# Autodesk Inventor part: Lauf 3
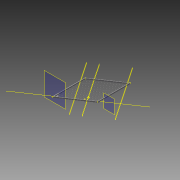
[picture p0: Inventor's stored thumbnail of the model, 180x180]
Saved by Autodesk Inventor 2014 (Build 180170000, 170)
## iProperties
Created: 2013-09
Part Number: Lauf 3
Material: Edelstahl
Document SubType Name: Modeling
Designer: Stefan Tammegger
Mass: 17798.4 g
Surface Area: 20213.9 cm^2
Volume: 2202.78 cm^3
Density: 8.08 g/cm^3
Appearance: Halbpoliert
Author: Stefan Tammegger
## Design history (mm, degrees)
node "Blöcke"
  sketch "FR 50 30 2"
    geometry: L1 (-39.377, 51.937)-(-65.377, 51.937); L2 (-67.377, 53.937)-(-67.377, 99.937); L3 (-65.377, 101.937)-(-39.377, 101.937); L4 (-37.377, 99.937)-(-37.377, 53.937); L5 (-39.377, 53.937)-(-65.377, 53.937); L6 (-65.377, 53.937)-(-65.377, 99.937); L7 (-65.377, 99.937)-(-39.377, 99.937); L8 (-39.377, 99.937)-(-39.377, 53.937); A1 r 2 centre (-39.377, 53.937) between (-39.377, 51.937) and (-37.377, 53.937); A2 r 2 centre (-39.377, 99.937) between (-37.377, 99.937) and (-39.377, 101.937); A3 r 2 centre (-65.377, 99.937) between (-65.377, 101.937) and (-67.377, 99.937); A4 r 2 centre (-65.377, 53.937) between (-67.377, 53.937) and (-65.377, 51.937); 4 further points
    constraints: 16 end point, 8 point on circle, 8 tangent, 6 point on line, 4 centre point, 4 parallel, 3 equal radius, 2 perpendicular, 1 horizontal, 1 midpoint, 3 other
    dimensions: "d0" = 30 distance of point (-67.377, 101.937) point (-37.377, 101.937); "d1" = 50 distance of point (-67.377, 51.937) point (-67.377, 101.937); "d2" = 2 distance between parallel lines of L2 L6; "d3" = 2 radius of A1
workplane "Arbeitsebene1"
sketch "Skizze1"
  geometry: L1 (-97, -165)-(-392, -165) reference; L2 (-127, -12)-(-127, -58) reference; 1 further point
  constraints: 1 vertical
  dimensions: "d4" = 10 dimension on L1
extrude "Extrusion1" new body sketch "Skizze1" stored distance "d5" = 3000; taper "d6" = 0 deg
workplane "Arbeitsebene2"
sketch "Skizze2"
  geometry: L1 (-75, 0)-(-75, 170) reference; L2 (1182, 10)-(1208, 10) reference; 1 further point
  constraints: 1 horizontal
  dimensions: "d7" = 30 dimension on L1
extrude "Extrusion2" new body sketch "Skizze2" stored distance "d8" = 3000; taper "d9" = 0 deg
workplane "Arbeitsebene3"
  workaxis "Arbeitsachse1"
  workpoint "Arbeitspunkt1"
workpoint "Arbeitspunkt2"
sketch "Skizze3"
  geometry: L1 (1307.343, 60)-(-1177.83, 60) reference; 2 further points
  constraints: 1 horizontal, 1 other
  dimensions: "d10" = 60 dimension on point (-144.968, 0)
extrude "Extrusion3" new body sketch "Skizze3" stored distance "d11" = 3000; taper "d12" = 0 deg
sketch "Skizze4"
  geometry: L1 (1004.976, 107)-(1004.976, 153) reference; L2 (1256.259, 60)-(-1228.914, 60) reference; 1 further point
  constraints: 1 horizontal
  dimensions: "d13" = 10 dimension on L1
extrude "Extrusion4" new body sketch "Skizze4" stored distance "d14" = 3000; taper "d15" = 0 deg
workplane "Arbeitsebene4"
feature "Trennen1"
feature "Trennen2"
workplane "Arbeitsebene5"
feature "Trennen3"
feature "Trennen4"
workplane "Arbeitsebene6"
feature "Trennen5"
feature "Trennen6"
workplane "Arbeitsebene7"
feature "Trennen7"
feature "Trennen8"
sketch "Skizze5"
  geometry: L1 (0, 0)-(0, 1504.053) reference; L2 (32, 297.735)-(-263, 297.735) reference; L3 (0, 217.735)-(-80, 217.735); L4 (-80, 217.735)-(-80, 97.735); L5 (-80, 97.735)-(0, 97.735); L6 (0, 97.735)-(0, 217.735); 1 further point
  constraints: 8 end point, 2 parallel, 1 collinear, 1 horizontal, 1 perpendicular
  dimensions: "d16" = 80 distance of L5.end L4.end; "d17" = 120 distance of L4.end L3.end; "d18" = 80 distance between parallel lines of L3 L2
  node "Referenz5"
workplane "Arbeitsebene8"
extrude "Extrusion5" new body sketch "Skizze5" stored distance "d19" = 3000; taper "d20" = 0 deg
hole "Bohrung1" diameter "d23" = 12; stored, may be unused: countersink angle "d27" = 90 deg, drill point angle "d29" = 118 deg; dims "d21" = 20, "d22" = 20, "d24" = 6, "d25" = 4, "d26" = 2, "d28" = 8
hole "Bohrung2" diameter "d32" = 12; stored, may be unused: countersink angle "d36" = 90 deg, drill point angle "d38" = 118 deg; dims "d30" = 20, "d31" = 20, "d33" = 6, "d34" = 4, "d35" = 2, "d37" = 8
sketch "Skizze6"
  geometry: L1 (0, 1504.053)-(0, 0) reference; L2 (183, 161.82)-(43, 161.82) reference; L3 (80, 120)-(0, 120); L4 (0, 120)-(0, 0); L5 (0, 0)-(80, 0); L6 (80, 0)-(80, 120); 1 further point
  constraints: 8 end point, 2 parallel, 1 collinear, 1 horizontal, 1 perpendicular
  dimensions: "d39" = 80 distance of L5.end L4.end; "d40" = 120 distance of L4.end L3.end; "d41" = 0 distance from line of L5 L1.end
  node "Referenz6"
workplane "Arbeitsebene9"
extrude "Extrusion6" new body sketch "Skizze6" stored distance "d42" = 3000; taper "d43" = 0 deg
hole "Bohrung3" diameter "d46" = 12; stored, may be unused: countersink angle "d50" = 90 deg, drill point angle "d52" = 118 deg; dims "d44" = 20, "d45" = 20, "d47" = 6, "d48" = 4, "d49" = 2, "d51" = 8
hole "Bohrung4" diameter "d55" = 12; stored, may be unused: countersink angle "d59" = 90 deg, drill point angle "d61" = 118 deg; dims "d53" = 20, "d54" = 20, "d56" = 6, "d57" = 4, "d58" = 2, "d60" = 8
sketch "Skizze7" dims "d70" = 10
  geometry: L1 (984.976, 12)-(984.976, 58) reference; L2 (-204.968, 58)-(-204.968, 12) reference; L3 (984.976, 58)-(-204.968, 58) reference; L4 (984.976, 12)-(-204.968, 12) reference; L5 (984.976, 35)-(-204.968, 35); C1 r 2.5 at (852.76, 35); C2 r 2.5 at (720.544, 35); C3 r 2.5 at (588.328, 35); C4 r 2.5 at (456.112, 35); C5 r 2.5 at (323.896, 35); C6 r 2.5 at (191.68, 35); C7 r 2.5 at (59.464, 35); C8 r 2.5 at (-72.752, 35); 1 further point
  constraints: 8 centre point, 2 end point, 2 midpoint, 1 horizontal, 1 point on line, 14 other
  dimensions: "d62" = 5 diameter of C1; "d63" = 1189.94441 distance of L5.end L5.start (derived); "d64" = 132.21605 distance of C1.centre L5.start (= 0.111111 x d63); "d67" = 132.216 distance of C1.centre C2.centre
extrude "Extrusion7" new body sketch "Skizze7" stored distance "d72" = 3000; taper "d73" = 0 deg
sketch "Skizze8"
  geometry: 9 further points; 8 other entities
  constraints: 8 other
hole "Bohrung5" sketch "Skizze8" at (23, 1313.061), (23, 1153.456), (23, 993.85), (23, 834.244), (23, 674.638), (23, 515.033), (23, 355.427), (23, 195.821) diameter "d74" = 6; stored, may be unused: countersink angle "d78" = 90 deg, drill point angle "d80" = 118 deg; dims "d75" = 6, "d76" = 4, "d77" = 2, "d79" = 8
sketch "Skizze9"
  geometry: 9 further points; 8 other entities
  constraints: 8 other
hole "Bohrung6" sketch "Skizze9" at (23, -195.821), (23, -355.426), (23, -515.032), (23, -674.638), (23, -834.244), (23, -993.849), (23, -1153.455), (23, -1313.061) diameter "d81" = 6; stored, may be unused: countersink angle "d85" = 90 deg, drill point angle "d87" = 118 deg; dims "d82" = 6, "d83" = 4, "d84" = 2, "d86" = 8
workplane "Arbeitsebene10"
sketch "Skizze10"
  geometry: C1 r 5 at (852.76, 35); 2 further points; 1 other entity
  constraints: 1 centre point, 1 coincident, 1 other
  dimensions: "d89" = 10 diameter of C1
extrude "Extrusion8" new body sketch "Skizze10" stored distance "d90" = 3000; taper "d91" = 0 deg
sketch "Skizze11"
  geometry: C1 r 5 at (0, 0) reference; 1 further point
hole "Bohrung7" sketch "Skizze11" at (0, 0) diameter "d92" = 6; stored, may be unused: countersink angle "d96" = 90 deg, drill point angle "d98" = 118 deg; dims "d93" = 6, "d94" = 4, "d95" = 2, "d97" = 8
workplane "Arbeitsebene11"
sketch "Skizze12"
  geometry: C1 r 5 at (852.76, 35); 2 further points; 1 other entity
  constraints: 1 centre point, 1 coincident, 1 other
  dimensions: "d100" = 10 diameter of C1
extrude "Extrusion9" new body sketch "Skizze12" stored distance "d101" = 3000; taper "d102" = 0 deg
sketch "Skizze13"
  geometry: C1 r 5 at (0, 0) reference; 1 further point
hole "Bohrung8" sketch "Skizze13" at (0, 0) diameter "d103" = 6; stored, may be unused: countersink angle "d107" = 90 deg, drill point angle "d109" = 118 deg; dims "d104" = 6, "d105" = 4, "d106" = 2, "d108" = 8
pattern_linear "Rechteckige Anordnung1" dims "d112" = 159.606
node "Volumenkörper1"
node "Referenz1"
node "Referenz2"
node "Referenz3"
node "Volumenkörper2"
node "Volumenkörper3"
node "Referenz4"
node "Volumenkörper4"
node "Volumenkörper5"
node "Volumenkörper6"
node "Volumenkörper7"
node "Volumenkörper8"
node "Volumenkörper9"
node "FR 50 30 2:1" dims "d4" = 10
node "FR 50 30 2:2" dims "d7" = 30
node "FR 50 30 2:3" dims "d10" = 60
node "FR 50 30 2:4" dims "d13" = 10
other parameters: "d88" = -425
